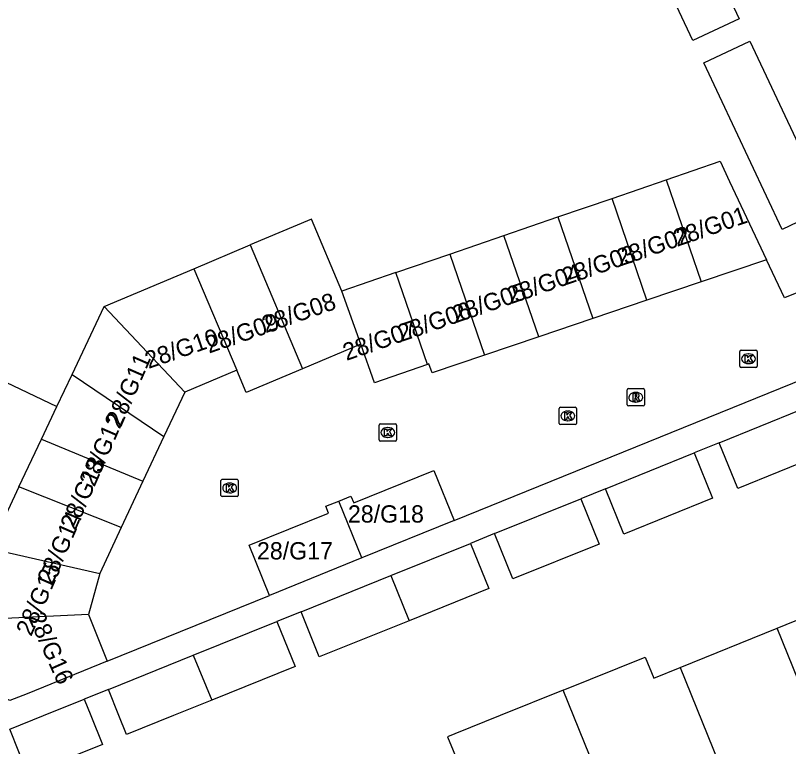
# Model space of a CAD drawing. Extents: x 162990 to 165007, y 383433 to 384336.
# Drawn here: x 163858.13 to 163902.75, y 383998.21 to 384040.43 of the extents above; entities that cross this region are included whole.
import ezdxf

# ---------------------------------------------------------------- set-up
doc = ezdxf.new("R2010")
doc.units = 0
for name, color, linetype in [('IMGEO_Kolk', 7, 'Continuous'), ('IMGEO_Pand', 7, 'Continuous'), ('IMGEO_Pand_nummerreeks', 7, 'Continuous'), ('IMGEO_Rijbaan_lokaal_open', 7, 'Continuous'), ('IMGEO_Rioolput', 7, 'Continuous'), ('IMGEO_Voetpad_open', 7, 'Continuous')]:
    doc.layers.add(name, color=color, linetype=linetype)

msp = doc.modelspace()

# ---------------------------------------------------------------- linework, layer by layer
at = {"layer": 'IMGEO_Kolk'}
for p, q in [((163899.932, 384020.177), (163899.932, 384021.029)), ((163900.007, 384021.103), (163900.859, 384021.103)), ((163900.933, 384021.029), (163900.933, 384020.177)), ((163900.42, 384020.883), (163900.445, 384020.883)), ((163900.859, 384020.103), (163900.007, 384020.103)), ((163900.443, 384020.323), (163900.418, 384020.323)), ((163889.581, 384017.803), (163890.433, 384017.803)), ((163889.506, 384016.877), (163889.506, 384017.729)), ((163889.994, 384017.583), (163890.019, 384017.583)), ((163890.507, 384017.729), (163890.507, 384016.877)), ((163890.017, 384017.023), (163889.992, 384017.023)), ((163879.115, 384015.922), (163879.115, 384016.774)), ((163879.19, 384016.848), (163880.042, 384016.848)), ((163879.603, 384016.628), (163879.628, 384016.628)), ((163880.116, 384016.774), (163880.116, 384015.922)), ((163890.433, 384016.803), (163889.581, 384016.803)), ((163879.626, 384016.068), (163879.601, 384016.068)), ((163880.042, 384015.848), (163879.19, 384015.848)), ((163869.989, 384012.718), (163869.989, 384013.57)), ((163870.064, 384013.644), (163870.916, 384013.644)), ((163870.477, 384013.424), (163870.502, 384013.424)), ((163870.99, 384013.57), (163870.99, 384012.718)), ((163870.916, 384012.644), (163870.064, 384012.644)), ((163870.5, 384012.864), (163870.475, 384012.864))]:
    msp.add_line(p, q, dxfattribs=at)
for points in [[(163899.932, 384020.177), (163899.932, 384021.029)], [(163900.007, 384021.103), (163900.859, 384021.103)], [(163900.933, 384021.029), (163900.933, 384020.177)], [(163900.253, 384020.803), (163900.376, 384020.803), (163900.376, 384020.652), (163900.506, 384020.803), (163900.67, 384020.803), (163900.524, 384020.652), (163900.677, 384020.403), (163900.525, 384020.403), (163900.44, 384020.567), (163900.376, 384020.5), (163900.376, 384020.403), (163900.253, 384020.403), (163900.253, 384020.803)], [(163900.859, 384020.103), (163900.007, 384020.103)], [(163889.581, 384017.803), (163890.433, 384017.803)], [(163889.506, 384016.877), (163889.506, 384017.729)], [(163889.827, 384017.503), (163889.95, 384017.503), (163889.95, 384017.352), (163890.08, 384017.503), (163890.244, 384017.503), (163890.098, 384017.352), (163890.251, 384017.103), (163890.099, 384017.103), (163890.014, 384017.267), (163889.95, 384017.2), (163889.95, 384017.103), (163889.827, 384017.103), (163889.827, 384017.503)], [(163890.507, 384017.729), (163890.507, 384016.877)], [(163879.115, 384015.922), (163879.115, 384016.774)], [(163879.19, 384016.848), (163880.042, 384016.848)], [(163879.436, 384016.548), (163879.559, 384016.548), (163879.559, 384016.397), (163879.689, 384016.548), (163879.853, 384016.548), (163879.707, 384016.397), (163879.86, 384016.148), (163879.708, 384016.148), (163879.623, 384016.312), (163879.559, 384016.245), (163879.559, 384016.148), (163879.436, 384016.148), (163879.436, 384016.548)], [(163880.116, 384016.774), (163880.116, 384015.922)], [(163890.433, 384016.803), (163889.581, 384016.803)], [(163880.042, 384015.848), (163879.19, 384015.848)], [(163869.989, 384012.718), (163869.989, 384013.57)], [(163870.064, 384013.644), (163870.916, 384013.644)], [(163870.31, 384013.344), (163870.433, 384013.344), (163870.433, 384013.193), (163870.563, 384013.344), (163870.727, 384013.344), (163870.581, 384013.193), (163870.734, 384012.944), (163870.582, 384012.944), (163870.497, 384013.108), (163870.433, 384013.041), (163870.433, 384012.944), (163870.31, 384012.944), (163870.31, 384013.344)], [(163870.99, 384013.57), (163870.99, 384012.718)], [(163870.916, 384012.644), (163870.064, 384012.644)]]:
    msp.add_lwpolyline(points, dxfattribs=at)
for centre, start, end in [((163900.009, 384021.027), 91.552, 178.448), ((163900.009, 384021.027), 91.552, 178.448), ((163900.857, 384021.027), 1.552, 88.448), ((163900.857, 384021.027), 1.552, 88.448), ((163900.009, 384020.179), 181.552, 268.448), ((163900.009, 384020.179), 181.552, 268.448), ((163900.857, 384020.179), 271.552, 358.448), ((163900.857, 384020.179), 271.552, 358.448), ((163889.583, 384017.727), 91.552, 178.448), ((163889.583, 384017.727), 91.552, 178.448), ((163890.431, 384017.727), 1.552, 88.448), ((163890.431, 384017.727), 1.552, 88.448), ((163879.192, 384016.772), 91.552, 178.448), ((163879.192, 384016.772), 91.552, 178.448), ((163880.04, 384016.772), 1.552, 88.448), ((163880.04, 384016.772), 1.552, 88.448), ((163889.583, 384016.879), 181.552, 268.448), ((163889.583, 384016.879), 181.552, 268.448), ((163890.431, 384016.879), 271.552, 358.448), ((163890.431, 384016.879), 271.552, 358.448), ((163879.192, 384015.924), 181.552, 268.448), ((163879.192, 384015.924), 181.552, 268.448), ((163880.04, 384015.924), 271.552, 358.448), ((163880.04, 384015.924), 271.552, 358.448), ((163870.066, 384013.568), 91.552, 178.448), ((163870.066, 384013.568), 91.552, 178.448), ((163870.914, 384013.568), 1.552, 88.448), ((163870.914, 384013.568), 1.552, 88.448), ((163870.066, 384012.72), 181.552, 268.448), ((163870.066, 384012.72), 181.552, 268.448), ((163870.914, 384012.72), 271.552, 358.448), ((163870.914, 384012.72), 271.552, 358.448)]:
    msp.add_arc(centre, 0.0765, start, end, dxfattribs=at)
for centre, major_axis, ratio, start_param, end_param in [((163900.419, 384020.603), (-0.387, 0.002), 0.722429, 4.712389, 7.853982), ((163900.444, 384020.603), (-0.39, 0.002), 0.717154, 1.570796, 4.712389), ((163889.993, 384017.303), (-0.387, 0.002), 0.722429, 4.712389, 7.853982), ((163890.018, 384017.303), (-0.39, 0.002), 0.717154, 1.570796, 4.712389), ((163879.602, 384016.348), (-0.387, 0.002), 0.722429, 4.712389, 7.853982), ((163879.627, 384016.348), (-0.39, 0.002), 0.717154, 1.570796, 4.712389), ((163870.476, 384013.144), (-0.387, 0.002), 0.722429, 4.712389, 7.853982), ((163870.501, 384013.144), (-0.39, 0.002), 0.717154, 1.570796, 4.712389)]:
    msp.add_ellipse(centre, major_axis=major_axis, ratio=ratio, start_param=start_param, end_param=end_param, dxfattribs=at)
at = {"layer": 'IMGEO_Pand'}
for points in [[(163895.007, 384043.699), (163897.772, 384044.748), (163899.897, 384040.243), (163897.231, 384038.985), (163895.007, 384043.699)], [(163897.85, 384037.688), (163900.51, 384038.942), (163905.043, 384029.332), (163902.383, 384028.078), (163897.85, 384037.688)], [(163895.677, 384030.936), (163898.796, 384032.007), (163899.347, 384030.838), (163901.478, 384026.314)], [(163892.559, 384029.866), (163895.677, 384030.936)], [(163895.677, 384030.936), (163897.702, 384025.039)], [(163889.44, 384028.795), (163892.559, 384029.866)], [(163894.578, 384023.985), (163892.559, 384029.866)], [(163876.966, 384024.513), (163875.212, 384028.668), (163871.679, 384027.177)], [(163886.322, 384027.725), (163889.44, 384028.795)], [(163889.44, 384028.795), (163891.454, 384022.93)], [(163883.203, 384026.654), (163886.322, 384027.725)], [(163888.33, 384021.875), (163886.322, 384027.725)], [(163868.423, 384025.802), (163871.679, 384027.177)], [(163871.679, 384027.177), (163874.697, 384020.022)], [(163880.085, 384025.584), (163883.203, 384026.654)], [(163883.203, 384026.654), (163885.206, 384020.821)], [(163901.478, 384026.314), (163897.702, 384025.039)], [(163863.252, 384023.62), (163868.423, 384025.802)], [(163868.423, 384025.802), (163870.896, 384019.938)], [(163880.085, 384025.584), (163876.966, 384024.513)], [(163881.907, 384020.275), (163880.085, 384025.584)], [(163897.702, 384025.039), (163894.578, 384023.985)], [(163878.058, 384021.439), (163876.966, 384024.513)], [(163861.392, 384019.691), (163863.252, 384023.62)], [(163867.897, 384018.685), (163863.252, 384023.62)], [(163894.578, 384023.985), (163891.454, 384022.93)], [(163891.454, 384022.93), (163888.33, 384021.875)], [(163888.33, 384021.875), (163885.206, 384020.821)], [(163878.058, 384021.439), (163874.697, 384020.022)], [(163881.907, 384020.275), (163878.85, 384019.212), (163878.058, 384021.439)], [(163885.206, 384020.821), (163882.179, 384019.799), (163881.986, 384020.303), (163881.907, 384020.275)], [(163855.856, 384020.062), (163860.522, 384017.854)], [(163874.697, 384020.022), (163871.44, 384018.648), (163870.896, 384019.938)], [(163860.522, 384017.854), (163861.392, 384019.691)], [(163861.392, 384019.691), (163866.698, 384016.124)], [(163870.896, 384019.938), (163867.897, 384018.685)], [(163867.897, 384018.685), (163866.698, 384016.124)], [(163859.625, 384015.959), (163860.522, 384017.854)], [(163898.746, 384015.746), (163903.482, 384017.669)], [(163866.698, 384016.124), (163865.487, 384013.539)], [(163858.324, 384013.211), (163859.625, 384015.959)], [(163859.625, 384015.959), (163865.487, 384013.539)], [(163904.546, 384015.044), (163899.811, 384013.122), (163898.746, 384015.746)], [(163892.18, 384013.09), (163897.293, 384015.166)], [(163897.293, 384015.166), (163898.353, 384012.556), (163893.239, 384010.48), (163892.18, 384013.09)], [(163876.791, 384012.387), (163877.492, 384012.671), (163877.649, 384012.281), (163882.283, 384014.16), (163883.455, 384011.268)], [(163865.487, 384013.539), (163864.232, 384010.859)], [(163858.324, 384013.211), (163856.642, 384009.659)], [(163864.232, 384010.859), (163858.324, 384013.211)], [(163885.785, 384010.509), (163890.765, 384012.519)], [(163890.765, 384012.519), (163891.821, 384009.908), (163886.84, 384007.899), (163885.785, 384010.509)], [(163872.788, 384006.942), (163871.616, 384009.834), (163876.204, 384011.695), (163876.047, 384012.085), (163876.791, 384012.387)], [(163878.122, 384009.105), (163876.791, 384012.387)], [(163883.455, 384011.268), (163878.122, 384009.105)], [(163864.232, 384010.859), (163862.993, 384008.214)], [(163879.788, 384008.089), (163884.385, 384009.944)], [(163884.385, 384009.944), (163885.44, 384007.334), (163880.843, 384005.48)], [(163856.642, 384009.659), (163862.993, 384008.214)], [(163878.122, 384009.105), (163872.788, 384006.942)], [(163862.993, 384008.214), (163862.336, 384005.843)], [(163874.611, 384006), (163879.788, 384008.089)], [(163879.788, 384008.089), (163880.843, 384005.48)], [(163902.084, 384005.049), (163907.678, 384007.32)], [(163862.336, 384005.843), (163854.665, 384005.482)], [(163862.336, 384005.843), (163863.429, 384003.146)], [(163880.843, 384005.48), (163875.666, 384003.391), (163874.611, 384006)], [(163868.392, 384003.49), (163873.22, 384005.438)], [(163873.22, 384005.438), (163874.274, 384002.83), (163869.463, 384000.89)], [(163896.496, 384002.78), (163902.084, 384005.049)], [(163906.07, 383995.217), (163902.084, 384005.049)], [(163863.429, 384003.146), (163858.796, 384001.267), (163857.813, 384000.868), (163853.457, 384002.931)], [(163863.492, 384001.512), (163868.392, 384003.49)], [(163868.392, 384003.49), (163869.463, 384000.89)], [(163889.748, 384001.466), (163894.477, 384003.373), (163894.969, 384002.16), (163896.496, 384002.78)], [(163896.496, 384002.78), (163899.978, 383994.175)], [(163869.463, 384000.89), (163867.258, 384000), (163864.546, 383998.906), (163864.104, 384000), (163863.492, 384001.512)], [(163889.748, 384001.466), (163886.113, 384000), (163883.488, 383998.941), (163883.071, 383998.773), (163883.712, 383997.189)], [(163893.721, 383991.644), (163889.748, 384001.466)], [(163858.852, 383996.609), (163857.798, 383999.214), (163859.746, 384000), (163862.092, 384000.947)], [(163862.092, 384000.947), (163862.475, 384000), (163863.146, 383998.341), (163858.852, 383996.609)]]:
    msp.add_lwpolyline(points, dxfattribs=at)
at = {"layer": 'IMGEO_Rijbaan_lokaal_open'}
for points in [[(163930.377, 384035.386), (163902.507, 384024.128), (163901.478, 384026.314)], [(163883.455, 384011.268), (163926.713, 384028.812)], [(163863.429, 384003.146), (163872.788, 384006.942)]]:
    msp.add_lwpolyline(points, dxfattribs=at)
at = {"layer": 'IMGEO_Rioolput'}
for p, q in [((163893.426, 384017.954), (163893.426, 384018.806)), ((163893.501, 384018.88), (163894.353, 384018.88)), ((163894.427, 384018.806), (163894.427, 384017.954)), ((163893.914, 384018.66), (163893.939, 384018.66)), ((163894.353, 384017.88), (163893.501, 384017.88)), ((163893.937, 384018.1), (163893.912, 384018.1))]:
    msp.add_line(p, q, dxfattribs=at)
for points in [[(163893.426, 384017.954), (163893.426, 384018.806)], [(163893.501, 384018.88), (163894.353, 384018.88)], [(163894.427, 384018.806), (163894.427, 384017.954)], [(163894.015, 384018.578), (163893.763, 384018.58), (163893.763, 384018.18)], [(163893.763, 384018.18), (163893.887, 384018.18), (163893.887, 384018.342), (163893.898, 384018.342)], [(163893.941, 384018.499), (163893.887, 384018.499), (163893.887, 384018.418)], [(163893.887, 384018.418), (163893.939, 384018.418)], [(163893.945, 384018.313), (163894.016, 384018.18), (163894.156, 384018.18), (163894.091, 384018.306)], [(163894.353, 384017.88), (163893.501, 384017.88)]]:
    msp.add_lwpolyline(points, dxfattribs=at)
for centre, radius, start, end in [((163893.503, 384018.804), 0.0765, 91.552, 178.448), ((163893.503, 384018.804), 0.0765, 91.552, 178.448), ((163894.351, 384018.804), 0.0765, 1.552, 88.448), ((163894.351, 384018.804), 0.0765, 1.552, 88.448), ((163893.897, 384018.289), 0.0533, 26.0293, 88.6989), ((163893.923, 384018.607), 0.19, 274.7715, 282.9687), ((163893.947, 384018.403), 0.0964, 77.0061, 93.1865), ((163893.961, 384018.46), 0.0378, 276.6634, 79.6772), ((163894.014, 384018.468), 0.109, 350.3612, 89.416), ((163894.012, 384018.468), 0.112, 277.5842, 350.9817), ((163893.996, 384018.253), 0.108, 29.5134, 73.7905), ((163893.503, 384017.956), 0.0765, 181.552, 268.448), ((163893.503, 384017.956), 0.0765, 181.552, 268.448), ((163894.351, 384017.956), 0.0765, 271.552, 358.448), ((163894.351, 384017.956), 0.0765, 271.552, 358.448)]:
    msp.add_arc(centre, radius, start, end, dxfattribs=at)
for centre, major_axis, ratio, start_param, end_param in [((163893.913, 384018.38), (-0.387, 0.002), 0.722429, 4.712389, 7.853982), ((163893.938, 384018.38), (-0.39, 0.002), 0.717154, 1.570796, 4.712389)]:
    msp.add_ellipse(centre, major_axis=major_axis, ratio=ratio, start_param=start_param, end_param=end_param, dxfattribs=at)
at = {"layer": 'IMGEO_Voetpad_open'}
for points in [[(163898.746, 384015.746), (163897.293, 384015.166)], [(163892.18, 384013.09), (163890.765, 384012.519)], [(163885.785, 384010.509), (163884.385, 384009.944)], [(163874.611, 384006), (163873.22, 384005.438)], [(163863.492, 384001.512), (163862.092, 384000.947)]]:
    msp.add_lwpolyline(points, dxfattribs=at)

# ---------------------------------------------------------------- texts
at = {"layer": 'IMGEO_Pand_nummerreeks'}
for s, rotation, p in [('28/G01', 19.0369, (163896.306, 384027.062)), ('28/G02', 19.0369, (163893.035, 384025.933)), ('28/G03', 19.0369, (163889.879, 384024.844)), ('28/G04', 19.0369, (163886.717, 384023.753)), ('28/G05', 19.0369, (163883.556, 384022.662)), ('28/G08', 19.0394, (163872.566, 384022.077)), ('28/G06', 19.0369, (163880.394, 384021.571)), ('28/G09', 19.0369, (163869.3, 384020.903)), ('28/G07', 19.0394, (163877.233, 384020.48)), ('28/G10', 19.0369, (163865.81, 384020.016)), ('28/G11', 66.4155, (163864.216, 384016.608)), ('28/G12', 66.4155, (163862.686, 384013.165)), ('28/G13', 66.4155, (163861.585, 384010.644)), ('28/G14', 66.4155, (163860.26, 384007.504)), ('28/G15', 66.4155, (163859.034, 384004.534)), ('28/G16', 293.9625, (163858.83, 384005.712))]:
    msp.add_text(s, height=1, rotation=rotation, dxfattribs=at).set_placement(p)
for s, p in [('28/G18', (163877.317, 384011.145)), ('28/G17', (163872.066, 384009.017))]:
    msp.add_text(s, height=1, dxfattribs=at).set_placement(p)

doc.saveas('drawing.dxf')
